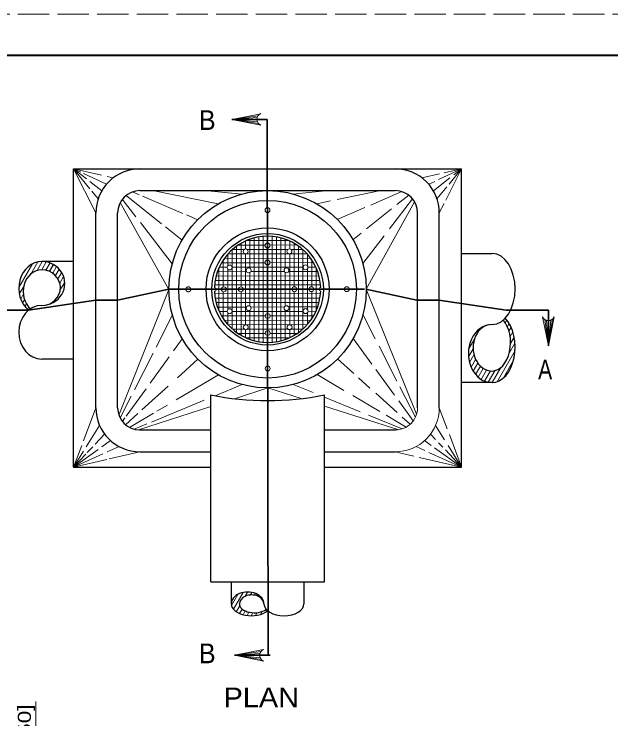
# Model space of a CAD drawing. Extents: x 750.7 to 784.7, y 860.1 to 882.1.
# Drawn here: x 766.8 to 774.08, y 873.51 to 882.12 of the extents above; entities that cross this region are included whole.
import ezdxf
from ezdxf.enums import TextEntityAlignment as Align

# ---------------------------------------------------------------- set-up
doc = ezdxf.new("R2010")
doc.units = 0
doc.header["$LTSCALE"] = 0.064
doc.linetypes.add('DASH_DOUBLE_DOT', pattern=[9.2, 5, -1.2, 0.3, -1.2, 0.3, -1.2])
doc.linetypes.add('LONG_DASHED', pattern=[7.5, 6, -1.5])
doc.layers.add('1', color=7, linetype='Continuous', lineweight=13)

msp = doc.modelspace()

# ---------------------------------------------------------------- linework, layer by layer
at = {"layer": '1', "lineweight": 25}
for p, q in [((752.65083, 881.61842), (784.15083, 881.61842)), ((767.52283, 880.22925), (772.25958, 880.22925)), ((767.52283, 876.58575), (767.52283, 880.22925)), ((772.25958, 876.58575), (772.25958, 880.22925)), ((768.332, 879.96292), (771.45042, 879.96292)), ((767.79475, 877.31208), (767.79475, 879.69192)), ((768.06092, 877.31208), (768.06092, 879.69192)), ((771.72142, 877.31208), (771.72142, 879.69192)), ((771.98767, 877.31208), (771.98767, 879.69192)), ((772.25958, 879.19567), (772.63092, 879.19567)), ((767.52283, 879.09792), (767.13475, 879.09792)), ((767.22817, 878.97692), (767.27658, 879.06117)), ((767.52283, 877.90608), (767.13475, 877.90608)), ((772.63092, 877.61933), (772.25958, 877.61933)), ((769.19675, 875.187), (769.19675, 877.46867)), ((770.58558, 875.187), (770.58558, 877.46867)), ((768.332, 877.041), (769.19675, 877.041)), ((770.58558, 877.041), (771.45042, 877.041)), ((768.33208, 876.77467), (769.19675, 876.77467)), ((770.58558, 876.77467), (771.45033, 876.77467)), ((767.52283, 876.58575), (769.19675, 876.58575)), ((770.58558, 876.58575), (772.25958, 876.58575)), ((769.19675, 875.187), (770.58558, 875.187)), ((769.44733, 875.187), (769.44733, 874.91725)), ((770.33508, 875.187), (770.33508, 874.91725)), ((769.8765, 874.82292), (769.88567, 874.83892))]:
    msp.add_line(p, q, dxfattribs=at)
at = {"layer": '1'}
for p, q in [((769.77508, 880.87667), (769.45442, 880.83183)), ((769.76425, 880.85442), (769.45442, 880.83183)), ((769.76092, 880.83183), (769.45442, 880.83183)), ((769.76658, 880.803), (769.45442, 880.83183)), ((769.77883, 880.78225), (769.45442, 880.83183)), ((767.79475, 879.69192), (767.52283, 880.22925)), ((767.72308, 879.98608), (767.52283, 880.22925)), ((767.68167, 880.10558), (767.52283, 880.22925)), ((767.613, 880.18667), (767.52283, 880.22925)), ((767.86183, 880.15333), (767.52283, 880.22925)), ((767.92308, 880.04042), (767.64517, 880.1715)), ((771.77442, 880.1205), (771.99058, 880.169)), ((771.9795, 880.09708), (772.25958, 880.22925)), ((772.04708, 880.18167), (772.25958, 880.22925)), ((772.06542, 879.84567), (772.25958, 880.22925)), ((772.10692, 880.04383), (772.25958, 880.22925)), ((772.16375, 880.15467), (772.25958, 880.22925)), ((768.008, 880.1205), (767.93275, 880.13742)), ((771.91525, 879.96125), (772.1165, 880.11783)), ((767.86708, 879.96125), (767.7205, 880.07542)), ((771.85933, 880.04042), (771.93192, 880.07467)), ((771.95917, 879.8645), (772.0795, 880.01058)), ((767.82317, 879.8645), (767.74742, 879.9565)), ((768.32467, 879.91283), (768.24275, 879.94783)), ((769.28742, 879.79992), (768.48692, 879.96292)), ((769.57758, 879.92067), (769.123, 879.96292)), ((770.20067, 879.92175), (770.6335, 879.96292)), ((770.74217, 879.85367), (771.27367, 879.96292)), ((771.15167, 879.7875), (771.53158, 879.9505)), ((771.47042, 879.79275), (771.61425, 879.90783)), ((768.28425, 879.64208), (768.11758, 879.85775)), ((768.59683, 879.55825), (768.163, 879.90383)), ((768.85742, 879.68542), (768.364, 879.89608)), ((770.49125, 879.802), (770.65908, 879.83658)), ((771.09567, 878.76075), (771.68592, 879.826)), ((771.38108, 879.4985), (771.66075, 879.86283)), ((768.68742, 878.75633), (768.093, 879.81975)), ((770.74092, 879.61117), (771.07883, 879.75625)), ((771.09792, 879.49458), (771.40333, 879.739)), ((771.98767, 879.69192), (772.04492, 879.805)), ((769.0385, 879.60817), (768.90133, 879.66667)), ((768.72783, 879.06792), (768.33842, 879.57192)), ((768.84758, 879.3585), (768.6445, 879.52033)), ((769.78317, 878.11892), (769.78317, 879.398)), ((769.83717, 878.11208), (769.83717, 879.40483)), ((769.89117, 879.32292), (769.89117, 879.40708)), ((769.94525, 878.11208), (769.94525, 879.40483)), ((769.99925, 878.11892), (769.99925, 879.398)), ((770.93317, 879.36267), (771.0335, 879.44292)), ((771.05408, 879.07242), (771.3135, 879.41042)), ((769.56708, 878.78767), (769.56708, 879.32025)), ((769.62108, 879.25075), (769.62108, 879.34817)), ((769.63008, 879.35217), (770.15008, 879.35317)), ((769.67508, 879.01483), (769.67508, 879.37)), ((769.72917, 878.13042), (769.72917, 879.3865)), ((770.05325, 878.13042), (770.05325, 879.3865)), ((770.10725, 879.01625), (770.10725, 879.37)), ((770.16133, 879.25158), (770.16133, 879.34817)), ((770.21533, 878.78892), (770.21533, 879.32025)), ((769.459, 878.27475), (769.459, 879.24208)), ((769.46092, 879.24383), (769.60408, 879.24408)), ((769.51308, 878.2315), (769.51308, 879.28542)), ((769.53117, 879.298), (769.86075, 879.29858)), ((769.64192, 879.24417), (770.13858, 879.24508)), ((769.89117, 879.11542), (769.89117, 879.26292)), ((769.91967, 879.29867), (770.24917, 879.29933)), ((770.17642, 879.24517), (770.31958, 879.24542)), ((770.26933, 878.2315), (770.26933, 879.28542)), ((770.32333, 878.27475), (770.32333, 879.24208)), ((769.3635, 879.13558), (770.4175, 879.13758)), ((769.405, 879.04433), (769.405, 879.18775)), ((769.40667, 879.18967), (770.37408, 879.1915)), ((769.62108, 878.32483), (769.62108, 879.19092)), ((770.16133, 878.326), (770.16133, 879.19208)), ((770.37733, 879.04483), (770.37733, 879.18775)), ((766.85417, 878.78117), (767.01967, 879.06908)), ((767.00067, 878.94508), (767.08558, 879.09283)), ((767.07733, 878.9875), (767.14075, 879.09783)), ((767.13458, 878.99608), (767.19008, 879.09267)), ((767.18392, 878.99092), (767.23517, 879.08017)), ((769.32875, 879.0815), (769.86075, 879.0825)), ((769.351, 878.78692), (769.351, 879.1175)), ((769.89117, 878.4615), (769.89117, 879.05542)), ((769.92042, 879.08258), (770.45242, 879.08367)), ((770.43142, 878.78892), (770.43142, 879.1175)), ((767.26783, 878.955), (767.31433, 879.03592)), ((767.30292, 878.92508), (767.34825, 879.00392)), ((767.33267, 878.88592), (767.37767, 878.96417)), ((769.27925, 878.97333), (769.63367, 878.974)), ((769.297, 878.49842), (769.297, 879.0185)), ((769.301, 879.02742), (769.39792, 879.02758)), ((769.405, 878.50858), (769.405, 879.00533)), ((769.45767, 879.02775), (770.32367, 879.02933)), ((769.67508, 878.553), (769.67508, 878.96358)), ((769.6855, 878.97417), (770.09608, 878.97492)), ((770.10725, 878.55333), (770.10725, 878.96392)), ((770.14792, 878.975), (770.50233, 878.97567)), ((770.37733, 878.51158), (770.37733, 879.00833)), ((770.38342, 879.0295), (770.48042, 879.02967)), ((770.48542, 878.49842), (770.48542, 879.0185)), ((767.35483, 878.83358), (767.40125, 878.91417)), ((769.26283, 878.91933), (770.51892, 878.92167)), ((766.86033, 878.70092), (766.91392, 878.79408)), ((767.3605, 878.75242), (767.41492, 878.847)), ((769.24475, 878.81125), (770.53742, 878.81367)), ((769.25142, 878.86525), (770.53058, 878.86767)), ((768.68742, 878.75633), (768.07667, 877.22117)), ((769.24492, 878.70317), (770.53767, 878.70567)), ((769.26508, 878.75725), (769.32667, 878.75742)), ((769.351, 878.39942), (769.351, 878.728)), ((769.38675, 878.7575), (769.53425, 878.75775)), ((769.56708, 878.19667), (769.56708, 878.728)), ((769.59425, 878.75792), (770.18817, 878.759)), ((770.21533, 878.19658), (770.21533, 878.72917)), ((770.24817, 878.75908), (770.39567, 878.75942)), ((770.43142, 878.39942), (770.43142, 878.73)), ((770.45567, 878.7595), (770.51733, 878.75967)), ((771.09567, 878.76075), (771.70958, 877.23267)), ((766.87725, 878.63942), (766.90933, 878.69517)), ((766.90067, 878.58917), (766.92417, 878.63008)), ((769.25183, 878.64917), (770.53092, 878.65158)), ((766.92892, 878.54733), (766.9475, 878.57975)), ((766.96117, 878.5125), (766.97675, 878.53958)), ((767.26983, 878.59467), (767.27925, 878.61108)), ((769.2635, 878.59517), (770.5195, 878.59758)), ((769.28008, 878.54125), (769.6345, 878.54192)), ((769.68633, 878.542), (770.09692, 878.54275)), ((770.14875, 878.54283), (770.50317, 878.5435)), ((768.729, 878.44483), (768.52958, 878.05133)), ((769.302, 878.48725), (769.39892, 878.48742)), ((769.405, 878.32908), (769.405, 878.47208)), ((769.45867, 878.4875), (770.32475, 878.48917)), ((769.67508, 878.14692), (769.67508, 878.50067)), ((770.10725, 878.14692), (770.10725, 878.502)), ((770.37733, 878.32908), (770.37733, 878.47258)), ((770.38442, 878.48925), (770.48142, 878.4895)), ((771.0545, 878.449), (771.20592, 878.15283)), ((769.33, 878.43325), (769.86192, 878.43425)), ((769.36492, 878.37933), (770.41892, 878.38133)), ((769.89117, 878.25392), (769.89117, 878.4015)), ((769.92167, 878.43442), (770.45367, 878.43542)), ((772.79283, 878.35008), (772.81267, 878.38458)), ((773.274, 878.38975), (773.31892, 878.06917)), ((773.29625, 878.37892), (773.31892, 878.06917)), ((773.3685, 878.3935), (773.31892, 878.06917)), ((773.34767, 878.38125), (773.31892, 878.06917)), ((773.31892, 878.37558), (773.31892, 878.06917)), ((769.40833, 878.32542), (770.37567, 878.32717)), ((769.64375, 878.27183), (770.14042, 878.27275)), ((770.17825, 878.27283), (770.32142, 878.27308)), ((772.47858, 878.25825), (772.49508, 878.28692)), ((772.818, 878.30283), (772.84083, 878.34267)), ((772.83808, 878.24692), (772.86533, 878.29433)), ((769.46275, 878.2715), (769.606, 878.27175)), ((769.53317, 878.21758), (769.86275, 878.21817)), ((769.62108, 878.16875), (769.62108, 878.26533)), ((769.89117, 878.10983), (769.89117, 878.194)), ((769.92167, 878.21833), (770.25125, 878.21892)), ((770.16125, 878.16875), (770.16133, 878.26617)), ((772.85208, 878.18025), (772.88583, 878.239)), ((768.84975, 878.15467), (768.74208, 878.00608)), ((769.63233, 878.16375), (770.15233, 878.16475)), ((770.93475, 878.15842), (771.16283, 877.84617)), ((772.34567, 878.027), (772.41633, 878.14983)), ((772.84092, 877.97892), (772.91142, 878.10158)), ((772.857, 878.09775), (772.90167, 878.17558)), ((771.25167, 878.06358), (771.46917, 877.63817)), ((772.34433, 877.93367), (772.40017, 878.03075)), ((768.49292, 877.979), (768.26617, 877.5315)), ((768.69075, 877.93517), (768.45617, 877.6115)), ((772.35667, 877.86417), (772.41075, 877.95833)), ((772.6925, 877.62975), (772.91192, 878.0115)), ((768.32308, 877.84067), (768.31892, 877.84233)), ((769.0415, 877.90575), (768.79125, 877.679)), ((770.74392, 877.90875), (770.94342, 877.72942)), ((772.37625, 877.80733), (772.43092, 877.90233)), ((772.40117, 877.75958), (772.45725, 877.85717)), ((772.77225, 877.67758), (772.89092, 877.884)), ((771.21308, 877.77733), (771.44117, 877.465)), ((772.43025, 877.71925), (772.48858, 877.82075)), ((772.46308, 877.6855), (772.52458, 877.79242)), ((772.49967, 877.65817), (772.56525, 877.77217)), ((772.54, 877.63742), (772.61133, 877.7615)), ((772.58458, 877.62392), (772.66542, 877.7645)), ((772.63425, 877.61933), (772.74017, 877.80367)), ((769.29117, 877.71483), (768.77475, 877.40875)), ((770.49492, 877.717), (770.8235, 877.52392)), ((771.00008, 877.6785), (771.14, 877.55267)), ((769.58175, 877.59508), (769.25017, 877.45825)), ((770.20483, 877.59625), (770.44917, 877.49642)), ((768.40733, 877.54408), (768.16475, 877.20925)), ((768.67908, 877.57742), (768.35692, 877.28558)), ((769.89333, 877.55467), (769.4865, 877.42225)), ((769.89333, 877.55467), (770.30283, 877.42308)), ((771.50508, 877.568), (771.69533, 877.196)), ((768.22725, 877.45475), (768.09158, 877.18692)), ((770.58558, 877.44067), (771.02308, 877.26192)), ((770.93017, 877.46117), (771.26025, 877.26717)), ((771.21092, 877.48892), (771.47183, 877.25433)), ((769.19675, 877.32792), (768.31658, 877.04142)), ((769.11742, 877.40342), (768.473, 877.13733)), ((768.66833, 877.34558), (768.53833, 877.26858)), ((770.58558, 877.33217), (771.49142, 877.041)), ((771.49167, 877.39583), (771.66942, 877.15242)), ((767.79475, 877.31208), (767.64283, 876.90625)), ((768.30925, 877.24242), (768.15733, 877.10483)), ((768.49892, 877.24525), (768.2065, 877.07183)), ((771.98767, 877.31208), (772.08433, 877.05392)), ((768.14975, 877.18858), (768.11833, 877.14525)), ((771.125, 877.22025), (771.5325, 877.05375)), ((771.33917, 877.22075), (771.5845, 877.0765)), ((771.53442, 877.19808), (771.63175, 877.11058)), ((767.67775, 876.83575), (767.83967, 877.09692)), ((768.41792, 877.11458), (768.262, 877.05017)), ((771.94275, 877.09692), (772.05192, 876.92075)), ((767.78467, 876.866), (767.90133, 876.99083)), ((771.88108, 876.99083), (771.94267, 876.92492)), ((772.11067, 876.98358), (772.25958, 876.58575)), ((767.86692, 876.83283), (767.97508, 876.91042)), ((771.80733, 876.91042), (771.88767, 876.85275)), ((767.68975, 876.76442), (767.75692, 876.83625)), ((767.93375, 876.77225), (768.07892, 876.83808)), ((771.7035, 876.83808), (771.81283, 876.7885)), ((771.9275, 876.82417), (772.25958, 876.58575)), ((771.97958, 876.88542), (772.02942, 876.83208)), ((772.09392, 876.85292), (772.25958, 876.58575)), ((767.52283, 876.58575), (767.8245, 876.80233)), ((767.52283, 876.58575), (767.64358, 876.78058)), ((767.52283, 876.58575), (767.8805, 876.74808)), ((767.95825, 876.68742), (768.33208, 876.77467)), ((771.67625, 876.72192), (771.45033, 876.77467)), ((771.86, 876.76708), (772.25958, 876.58575)), ((772.06192, 876.79733), (772.25958, 876.58575)), ((767.52283, 876.58575), (767.92933, 876.68067)), ((772.25958, 876.58575), (771.742, 876.70658)), ((769.44942, 874.8985), (769.52633, 875.03242)), ((769.47442, 874.85108), (769.59233, 875.05633)), ((769.61783, 875.00967), (769.64783, 875.06183)), ((769.679, 875.02508), (769.69742, 875.05717)), ((769.73017, 875.02317), (769.74233, 875.04433)), ((769.77483, 875.01), (769.78258, 875.02342)), ((769.81325, 874.98575), (769.81733, 874.99283)), ((769.50933, 874.82092), (769.55108, 874.89358)), ((769.54942, 874.79967), (769.58075, 874.85417)), ((769.59325, 874.78492), (769.6195, 874.83058)), ((769.64033, 874.77583), (769.66342, 874.81608)), ((769.69075, 874.77267), (769.71175, 874.80917)), ((769.74508, 874.77617), (769.76483, 874.81058)), ((769.80483, 874.78917), (769.825, 874.82433)), ((769.80908, 874.33417), (769.48842, 874.28933)), ((769.79817, 874.312), (769.48842, 874.28933)), ((769.79492, 874.28933), (769.48842, 874.28933)), ((769.80058, 874.2605), (769.48842, 874.28933)), ((769.81283, 874.23975), (769.48842, 874.28933)), ((767.06042, 872.42025), (767.06042, 873.72667))]:
    msp.add_line(p, q, dxfattribs=at)
at = {"layer": '1', "lineweight": 35}
for p, q in [((769.88733, 880.83183), (769.45442, 880.83183)), ((769.88733, 880.83183), (769.89958, 874.28933)), ((768.68667, 878.7595), (768.06092, 878.6265)), ((771.07283, 878.7595), (768.68667, 878.7595)), ((767.79475, 878.6265), (766.97333, 878.502)), ((768.06092, 878.6265), (767.79475, 878.6265)), ((766.97333, 878.502), (766.47842, 878.502)), ((772.80908, 878.502), (773.31892, 878.502)), ((773.31892, 878.502), (773.31892, 878.06917)), ((769.92125, 874.28933), (769.48842, 874.28933))]:
    msp.add_line(p, q, dxfattribs=at)
at = {"layer": '1', "linetype": 'LONG_DASHED'}
msp.add_lwpolyline([(750.65083, 860.11842), (784.65083, 860.11842), (784.65083, 882.11842), (750.65083, 882.11842)], close=True, dxfattribs=at)
at = {"layer": '1', "lineweight": 40}
msp.add_lwpolyline([(752.65083, 881.61842), (784.15083, 881.61842), (784.15083, 860.61842), (752.65083, 860.61842)], close=True, dxfattribs=at)
at = {"layer": '1'}
for points in [[(769.80858, 880.761), (769.45442, 880.83183), (769.80858, 880.90258)], [(773.38975, 878.42325), (773.31892, 878.06917), (773.24808, 878.42325)], [(767.62283, 876.85292), (767.52283, 876.58575), (767.67067, 876.744)], [(769.84258, 874.2185), (769.48842, 874.28933), (769.84258, 874.36017)]]:
    msp.add_lwpolyline(points, dxfattribs=at)
at = {"layer": '1', "lineweight": 35}
msp.add_lwpolyline([(771.08908, 878.7595), (771.71483, 878.6265), (771.98108, 878.6265), (772.80242, 878.502)], dxfattribs=at)
at = {"layer": '1', "lineweight": 25}
for centre, radius in [((769.89119, 878.75845), 1.2045), ((769.8912, 878.75845), 1.08447), ((769.8912, 878.75845), 0.75092), ((769.8912, 878.75845), 0.6809)]:
    msp.add_circle(centre, radius, dxfattribs=at)
at = {"layer": '1'}
for centre in [(769.89016, 879.72563), (769.89018, 879.29293), (769.62308, 879.22082), (770.15756, 879.22183), (769.42781, 879.02482), (769.89058, 879.08543), (770.35357, 879.02657), (769.65955, 878.98922), (770.12197, 878.9901), (770.21817, 878.75907), (770.42568, 878.75946), (769.35671, 878.75744), (769.56422, 878.75783), (769.66042, 878.5268), (770.12284, 878.52768), (769.42882, 878.49033), (769.89181, 878.43147), (770.35458, 878.49208), (769.62483, 878.29507), (770.15931, 878.29608), (769.89221, 878.22397), (769.89223, 877.79127)]:
    msp.add_circle(centre, 0.03001, dxfattribs=at)
at = {"layer": '1', "linetype": 'DASH_DOUBLE_DOT'}
for centre in [(770.85837, 878.75948), (768.92402, 878.75741)]:
    msp.add_circle(centre, 0.03001, dxfattribs=at)
at = {"layer": '1'}
for centre, radius, start, end in [((769.83721, 880.83187), 0.07644, 112.08782, 247.91395), ((769.24258, 878.75722), 0.02251, 271.10248, 89.11504), ((770.53981, 878.75967), 0.02251, 91.10124, 269.11531), ((773.31881, 878.45188), 0.07644, 202.08782, 337.91395), ((771.45031, 877.31205), 0.53736, 269.99993, 0.00003), ((771.4504, 877.31205), 0.27104, 269.99993, 0.00001), ((769.87118, 874.28942), 0.07644, 112.08782, 247.91395)]:
    msp.add_arc(centre, radius, start, end, dxfattribs=at)
at = {"layer": '1', "lineweight": 25}
for centre, radius, start, end in [((768.33208, 879.6919), 0.53736, 90.00002, 180.00003), ((771.4503, 879.6919), 0.53736, 0.00003, 90.00077), ((768.33199, 879.6919), 0.27104, 90.00002, 180.00002), ((771.4504, 879.6919), 0.27104, 0.00002, 90.00002), ((769.8912, 878.75845), 0.64861, 2.09623, 178.12011), ((769.8912, 878.75845), 0.64861, 182.09634, 358.12016), ((769.89119, 880.87287), 3.47429, 258.47052, 281.52957), ((768.33209, 877.31206), 0.53736, 180.00003, 269.99992), ((768.33199, 877.31206), 0.27104, 180.00003, 269.99993)]:
    msp.add_arc(centre, radius, start, end, dxfattribs=at)
for centre, major_axis, ratio, start_param, end_param in [((772.63094, 878.7622), (0, 0.43351), 0.651175, 3.1415927, 6.2831853), ((767.13474, 878.77014), (0, -0.32775), 0.856582, 3.1415927, 5.6706327), ((767.13474, 878.82974), (-0.28075, 0), 0.95517, 1.5707963, 4.712389), ((767.13474, 878.73055), (0, -0.26554), 0.856582, 3.1415948, 5.6320729), ((767.13474, 878.77883), (0.22746, 0), 0.95517, 4.712389, 7.8539816), ((767.13474, 878.23382), (0, -0.32775), 0.856582, 3.1415927, 6.2831853), ((772.63094, 878.05282), (0, 0.43351), 0.651175, 3.1415927, 5.6706321), ((772.63094, 878.10772), (0, 0.34725), 0.651175, 3.1415937, 5.63011), ((772.63094, 877.974), (0, 0.35469), 0.813326, 6.2831853, 9.424778), ((772.63094, 878.04458), (0, 0.28411), 0.813326, 6.2831853, 9.424778), ((769.64706, 874.91725), (0.19974, 0), 0.723868, 6.2831853, 9.424778), ((769.69674, 874.91725), (0.15007, 0), 0.723868, 6.2831853, 9.424778), ((769.69145, 874.91725), (0.24413, 0), 0.592259, 3.1415927, 5.6706342), ((769.73008, 874.91725), (0.18342, 0), 0.592259, 3.1415931, 5.6192748), ((770.09093, 874.91725), (0.24413, 0), 0.592259, 3.1415927, 6.2831853)]:
    msp.add_ellipse(centre, major_axis=major_axis, ratio=ratio, start_param=start_param, end_param=end_param, dxfattribs=at)

# ---------------------------------------------------------------- texts
at = {"layer": '1'}
for s, width, p in [('B', 0.95, (769.05342, 880.70425)), ('A', 0.8, (773.19392, 877.65942)), ('B', 0.95, (769.0535, 874.19267)), ('PLAN', 1.1, (769.353, 873.6555))]:
    msp.add_text(s, height=0.24, dxfattribs=dict(at, width=width)).set_placement(p)
at = {"layer": '1', "width": 1.3}
msp.add_text('6" [150]', height=0.16, rotation=90, dxfattribs=at).set_placement((767.00267, 873.21583), align=Align.CENTER)

doc.saveas('drawing.dxf')
